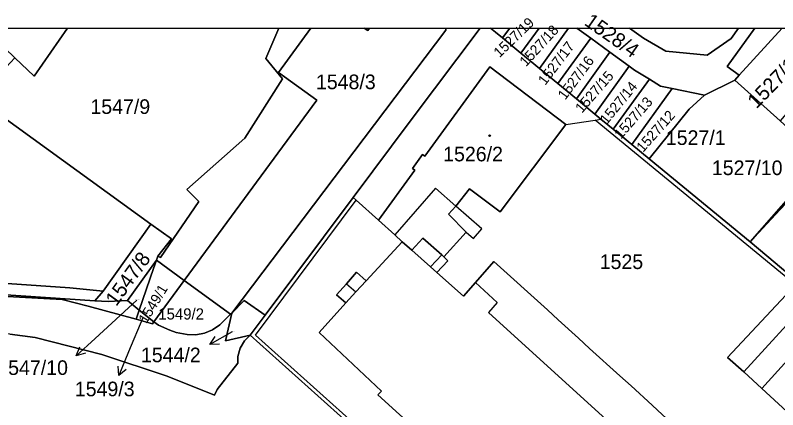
# Model space of a CAD drawing. Extents: x -598934 to -598196, y -1162208 to -1161502.
# Drawn here: x -598774.9 to -598686.2, y -1161549.6 to -1161503.7 of the extents above; entities that cross this region are included whole.
import ezdxf

# ---------------------------------------------------------------- set-up
doc = ezdxf.new("R2010")
doc.units = 0
for name, color, linetype in [('KN_CAR_KR', 7, 'Continuous'), ('KN_KULTURY', 7, 'Continuous'), ('KN_PARC_CIS_POM', 7, 'Continuous'), ('KN_PARC_CIS_POZ', 7, 'Continuous'), ('KN_PARC_CIS_STAV', 7, 'Continuous'), ('KN_PARC_PLOCHA', 7, 'Continuous'), ('PARC_C_SIPKA', 7, 'Continuous'), ('parcely_l', 7, 'Continuous')]:
    doc.layers.add(name, color=color, linetype=linetype)

msp = doc.modelspace()

# ---------------------------------------------------------------- linework, layer by layer
at = {"layer": 'KN_CAR_KR'}
for points in [[(-598710.83, -1161516.41), (-598707.43, -1161515.89)], [(-598707.43, -1161515.89), (-598706.75, -1161515.78)], [(-598684.14, -1161535.08), (-598707.43, -1161515.89)], [(-598726.01, -1161523.82), (-598730.74, -1161529.25)], [(-598723.64, -1161525.9), (-598726.01, -1161523.82)], [(-598746.92, -1161540.94), (-598735.22, -1161525.21)], [(-598735.56, -1161524.9), (-598735.22, -1161525.21)], [(-598735.22, -1161525.21), (-598732.63, -1161527.55)], [(-598720.59, -1161528.56), (-598723.64, -1161525.9)], [(-598722.41, -1161528.95), (-598721.57, -1161529.68)], [(-598721.57, -1161529.68), (-598720.59, -1161528.56)], [(-598728.73, -1161531.02), (-598726.58, -1161532.98)], [(-598726.58, -1161532.98), (-598725.27, -1161531.59)], [(-598726.58, -1161532.98), (-598725.82, -1161533.64)], [(-598736.36, -1161534.97), (-598735.27, -1161535.88)], [(-598735.27, -1161535.88), (-598734.05, -1161534.6)], [(-598721.34, -1161534.81), (-598718.81, -1161537.11)], [(-598736.43, -1161537.17), (-598735.27, -1161535.88)], [(-598690.13, -1161545.2), (-598682.28, -1161536.6)], [(-598718.81, -1161537.11), (-598719.81, -1161538.29)], [(-598719.81, -1161538.29), (-598700.16, -1161556.18)], [(-598688.04, -1161547.15), (-598679.81, -1161538.05)], [(-598713.19, -1161571.18), (-598746.92, -1161540.94)]]:
    msp.add_lwpolyline(points, dxfattribs=at)
at = {"layer": 'KN_KULTURY'}
for radius in [0.09, 0.0398]:
    msp.add_circle((-598719.7, -1161517.71), radius, dxfattribs=at)
at = {"layer": 'KN_PARC_PLOCHA'}
for points in [[(-598758.28, -1161531.72), (-598756.68, -1161529.73), (-598759.09, -1161528.02), (-598776.32, -1161515.51), (-598780.81, -1161514.88), (-598780.35, -1161514.34), (-598775.91, -1161509.73), (-598774.9, -1161508.67), (-598772.65, -1161510.8), (-598768.804, -1161505.182), (-598744.218, -1161505.182), (-598745.73, -1161508.71), (-598743.78, -1161511.08), (-598748.16, -1161518.02), (-598754.92, -1161523.98), (-598753.52, -1161525.38), (-598757.99, -1161531.9)], [(-598774.9, -1161508.67), (-598778.521, -1161505.182), (-598768.804, -1161505.182), (-598772.65, -1161510.8)], [(-598739.81, -1161513.56), (-598755.21, -1161534.56), (-598758.45, -1161532.21), (-598758.28, -1161531.72), (-598757.99, -1161531.9), (-598753.52, -1161525.38), (-598754.92, -1161523.98), (-598748.16, -1161518.02), (-598743.78, -1161511.08), (-598745.73, -1161508.71), (-598744.218, -1161505.182), (-598740.505, -1161505.182), (-598744.24, -1161510.34)], [(-598749.66, -1161538.35), (-598749.85, -1161538.48), (-598755.21, -1161534.56), (-598739.81, -1161513.56), (-598744.24, -1161510.34), (-598740.505, -1161505.182), (-598734.281, -1161505.182), (-598733.87, -1161505.48), (-598733.653, -1161505.182), (-598724.79, -1161505.182), (-598724.8, -1161505.44)], [(-598745.81, -1161538.62), (-598748.23, -1161536.88), (-598749.66, -1161538.35), (-598724.8, -1161505.44), (-598724.79, -1161505.182), (-598720.816, -1161505.182), (-598728.81, -1161515.85), (-598735.56, -1161524.9)], [(-598733.653, -1161505.182), (-598733.87, -1161505.48), (-598734.281, -1161505.182)], [(-598718.2, -1161506.34), (-598719.01, -1161505.67), (-598719.604, -1161505.182), (-598717.36, -1161505.182)], [(-598716.05, -1161508.11), (-598718.2, -1161506.34), (-598717.36, -1161505.182), (-598713.934, -1161505.182)], [(-598713.9, -1161509.88), (-598716.05, -1161508.11), (-598713.934, -1161505.182), (-598710.515, -1161505.182)], [(-598707.94, -1161506.37), (-598711.76, -1161511.65), (-598713.9, -1161509.88), (-598710.515, -1161505.182), (-598709.57, -1161505.182)], [(-598690.67, -1161510.67), (-598691.19, -1161511.24), (-598694.69, -1161513.01), (-598698.46, -1161512.22), (-598699.82, -1161511.93), (-598701.12, -1161511.13), (-598702.83, -1161510.09), (-598703.46, -1161509.63), (-598705.7, -1161508), (-598707.94, -1161506.37), (-598709.57, -1161505.182), (-598703.443, -1161505.182), (-598701.79, -1161506.37), (-598699.19, -1161507.89), (-598694.39, -1161508.34), (-598691.62, -1161506.42), (-598690.74, -1161505.182), (-598688.839, -1161505.182), (-598692.07, -1161509.66)], [(-598703.443, -1161505.182), (-598690.74, -1161505.182), (-598691.62, -1161506.42), (-598694.39, -1161508.34), (-598699.19, -1161507.89), (-598701.79, -1161506.37)], [(-598690.67, -1161510.67), (-598692.07, -1161509.66), (-598688.839, -1161505.182), (-598685.682, -1161505.182)], [(-598679.29, -1161508.89), (-598681.5, -1161511.01), (-598683.66, -1161513.34), (-598685.92, -1161515.99), (-598691.19, -1161511.24), (-598690.67, -1161510.67), (-598685.682, -1161505.182), (-598683.293, -1161505.182)], [(-598705.7, -1161508), (-598709.61, -1161513.42), (-598711.76, -1161511.65), (-598707.94, -1161506.37)], [(-598703.46, -1161509.63), (-598707.46, -1161515.19), (-598709.61, -1161513.42), (-598705.7, -1161508)], [(-598784.46, -1161519.18), (-598780.81, -1161514.88), (-598776.32, -1161515.51), (-598759.09, -1161528.02), (-598764.63, -1161535.79), (-598768.53, -1161535.41), (-598797.22, -1161533.44), (-598803.42, -1161532.39), (-598806.83, -1161531.59), (-598811.84, -1161530.11), (-598815.58, -1161528.74), (-598818.64, -1161527.27), (-598812.03, -1161518.31), (-598805.79, -1161510.18), (-598804.43, -1161511.1), (-598802.29, -1161510.38), (-598799.96, -1161510), (-598797.69, -1161510.09), (-598796.07, -1161510.41), (-598793.19, -1161511.82), (-598791.32, -1161513.23), (-598790.28, -1161514.28), (-598789.08, -1161516.12), (-598787.81, -1161519.11)], [(-598725.04, -1161531.81), (-598725.27, -1161531.59), (-598727.45, -1161529.65), (-598728.73, -1161531.02), (-598729.85, -1161530.05), (-598730.74, -1161529.25), (-598732.63, -1161527.55), (-598728.39, -1161521.72), (-598728.68, -1161521.52), (-598727.5, -1161519.9), (-598727.22, -1161520.1), (-598719.66, -1161509.71), (-598710.83, -1161516.41), (-598718.49, -1161526.57), (-598722.04, -1161523.9), (-598723.64, -1161525.9), (-598724.47, -1161526.85), (-598722.41, -1161528.95)], [(-598701.12, -1161511.13), (-598705.32, -1161516.95), (-598706.75, -1161515.78), (-598707.46, -1161515.19), (-598703.46, -1161509.63), (-598702.83, -1161510.09)], [(-598698.46, -1161512.22), (-598703.17, -1161518.72), (-598705.32, -1161516.95), (-598701.12, -1161511.13), (-598699.82, -1161511.93)], [(-598685.92, -1161515.99), (-598681, -1161520.47), (-598689.39, -1161530.06), (-598701.14, -1161520.39), (-598696.48, -1161514.62), (-598694.69, -1161513.01), (-598691.19, -1161511.24)], [(-598694.69, -1161513.01), (-598696.48, -1161514.62), (-598701.14, -1161520.39), (-598703.17, -1161518.72), (-598698.46, -1161512.22)], [(-598676.32, -1161516.24), (-598685.94, -1161526.36), (-598689.39, -1161530.06), (-598681, -1161520.47), (-598678.59, -1161517.73), (-598676.83, -1161515.79)], [(-598656.9, -1161534.24), (-598668.32, -1161547.09), (-598668.69, -1161546.9), (-598679.58, -1161538.19), (-598679.81, -1161538.05), (-598681.93, -1161536.28), (-598683.8, -1161534.76), (-598689.39, -1161530.06), (-598685.94, -1161526.36), (-598676.32, -1161516.24), (-598667.18, -1161524.65)], [(-598758.28, -1161531.72), (-598758.45, -1161532.21), (-598761.81, -1161536.9), (-598764.05, -1161537.02), (-598765.61, -1161536.92), (-598764.63, -1161535.79), (-598759.09, -1161528.02), (-598756.68, -1161529.73)], [(-598812.29, -1161531.38), (-598807.16, -1161532.91), (-598800.29, -1161534.3), (-598794.34, -1161535), (-598765.61, -1161536.92), (-598764.05, -1161537.02), (-598761.81, -1161536.9), (-598760.45, -1161538.01), (-598760.82, -1161539.08), (-598766.39, -1161537.57), (-598769.42, -1161536.76), (-598780.05, -1161536.18), (-598787.24, -1161536.14), (-598793.93, -1161535.43), (-598805.37, -1161534.38), (-598812.72, -1161531.83), (-598819.51, -1161528.42)], [(-598764.63, -1161535.79), (-598765.61, -1161536.92), (-598794.34, -1161535), (-598800.29, -1161534.3), (-598807.16, -1161532.91), (-598806.83, -1161531.59), (-598803.42, -1161532.39), (-598797.22, -1161533.44), (-598768.53, -1161535.41)], [(-598760.45, -1161538.01), (-598761.81, -1161536.9), (-598758.45, -1161532.21), (-598758.79, -1161533.17)], [(-598755.21, -1161534.56), (-598758.75, -1161539.39), (-598760.45, -1161538.01), (-598758.79, -1161533.17), (-598758.45, -1161532.21)], [(-598749.85, -1161538.48), (-598751.07, -1161539.71), (-598751.91, -1161540.31), (-598752.86, -1161540.7), (-598753.86, -1161540.88), (-598754.87, -1161540.85), (-598756.17, -1161540.61), (-598756.9, -1161540.34), (-598758.21, -1161539.76), (-598758.75, -1161539.39), (-598755.21, -1161534.56)], [(-598668.69, -1161546.9), (-598677.31, -1161556.9), (-598679.85, -1161554.66), (-598680.37, -1161555.18), (-598682.21, -1161553.52), (-598681.73, -1161552.97), (-598688.04, -1161547.15), (-598690.13, -1161545.2), (-598692.02, -1161543.52), (-598684.14, -1161535.08), (-598683.8, -1161534.76), (-598681.93, -1161536.28), (-598679.81, -1161538.05), (-598679.58, -1161538.19)], [(-598745.81, -1161538.62), (-598747.54, -1161540.94), (-598750.4, -1161541.58), (-598749.66, -1161538.35), (-598748.23, -1161536.88)], [(-598758.75, -1161539.39), (-598758.91, -1161539.61), (-598760.82, -1161539.08), (-598760.45, -1161538.01)]]:
    msp.add_lwpolyline(points, close=True, dxfattribs=at)
for points in [[(-598718.31, -1161567.16), (-598747.54, -1161540.94), (-598745.81, -1161538.62), (-598735.56, -1161524.9), (-598728.81, -1161515.85), (-598720.816, -1161505.182), (-598719.604, -1161505.182), (-598719.01, -1161505.67), (-598718.2, -1161506.34), (-598716.05, -1161508.11), (-598713.9, -1161509.88), (-598711.76, -1161511.65), (-598709.61, -1161513.42), (-598707.46, -1161515.19), (-598706.75, -1161515.78), (-598705.32, -1161516.95), (-598703.17, -1161518.72), (-598701.14, -1161520.39), (-598689.39, -1161530.06), (-598683.8, -1161534.76)], [(-598699.58, -1161550.19), (-598700.78, -1161549.06), (-598703.25, -1161546.81), (-598704.54, -1161545.68), (-598708.07, -1161542.47), (-598709.35, -1161541.28), (-598711.73, -1161539.15), (-598712.96, -1161537.99), (-598719.21, -1161532.36), (-598721.34, -1161534.81), (-598722.74, -1161536.38), (-598725.82, -1161533.64), (-598724.54, -1161532.27), (-598725.04, -1161531.81), (-598722.41, -1161528.95), (-598724.47, -1161526.85), (-598723.64, -1161525.9), (-598722.04, -1161523.9), (-598718.49, -1161526.57), (-598710.83, -1161516.41), (-598719.66, -1161509.71), (-598727.22, -1161520.1), (-598727.5, -1161519.9), (-598728.68, -1161521.52), (-598728.39, -1161521.72), (-598732.63, -1161527.55), (-598730.74, -1161529.25), (-598729.85, -1161530.05), (-598734.05, -1161534.6), (-598735.16, -1161533.58), (-598736.36, -1161534.97), (-598737.49, -1161536.23), (-598736.43, -1161537.17), (-598739.51, -1161540.6), (-598732.26, -1161547.43), (-598732.68, -1161547.89), (-598710.43, -1161568.09)], [(-598710.43, -1161568.09), (-598732.68, -1161547.89), (-598732.26, -1161547.43), (-598739.51, -1161540.6), (-598736.43, -1161537.17), (-598737.49, -1161536.23), (-598736.36, -1161534.97), (-598735.16, -1161533.58), (-598734.05, -1161534.6), (-598729.85, -1161530.05), (-598728.73, -1161531.02), (-598727.45, -1161529.65), (-598725.27, -1161531.59), (-598725.04, -1161531.81), (-598724.54, -1161532.27), (-598725.82, -1161533.64), (-598722.74, -1161536.38), (-598721.34, -1161534.81), (-598719.21, -1161532.36), (-598712.96, -1161537.99), (-598711.73, -1161539.15), (-598709.35, -1161541.28), (-598708.07, -1161542.47), (-598704.54, -1161545.68), (-598703.25, -1161546.81), (-598700.78, -1161549.06), (-598699.58, -1161550.19)], [(-598684.14, -1161535.08), (-598692.02, -1161543.52), (-598690.13, -1161545.2), (-598688.04, -1161547.15), (-598681.73, -1161552.97)], [(-598780.05, -1161536.18), (-598769.42, -1161536.76), (-598766.39, -1161537.57), (-598760.82, -1161539.08), (-598758.91, -1161539.61), (-598758.75, -1161539.39), (-598758.21, -1161539.76), (-598756.9, -1161540.34), (-598756.17, -1161540.61), (-598754.87, -1161540.85), (-598753.86, -1161540.88), (-598752.86, -1161540.7), (-598751.91, -1161540.31), (-598751.07, -1161539.71), (-598749.85, -1161538.48), (-598749.66, -1161538.35), (-598750.4, -1161541.58), (-598747.54, -1161540.94), (-598748.19, -1161541.59), (-598748.71, -1161542.44), (-598748.97, -1161543.41), (-598748.98, -1161544.17), (-598751.4, -1161547.24), (-598751.7, -1161547.91), (-598757.19, -1161545.72), (-598764.79, -1161543.19), (-598772.55, -1161541.22), (-598775.51, -1161540.82)], [(-598775.51, -1161540.82), (-598772.55, -1161541.22), (-598764.79, -1161543.19), (-598757.19, -1161545.72), (-598751.7, -1161547.91), (-598751.4, -1161547.24), (-598748.98, -1161544.17), (-598748.97, -1161543.41), (-598748.71, -1161542.44), (-598748.19, -1161541.59), (-598747.54, -1161540.94), (-598718.31, -1161567.16), (-598713.5, -1161571.51), (-598705.75, -1161578.52), (-598701.74, -1161583.54), (-598699.41, -1161586.46), (-598694.17, -1161593.02), (-598696.41, -1161595.1), (-598697.8, -1161597.55), (-598697.38, -1161599.8), (-598691.61, -1161616.39), (-598686.46, -1161632.58), (-598684.05, -1161640.04)]]:
    msp.add_lwpolyline(points, dxfattribs=at)
at = {"layer": 'PARC_C_SIPKA'}
for points in [[(-598760.72, -1161536.84), (-598765.56, -1161541.31), (-598767.764, -1161543.345)], [(-598760.04, -1161538.91), (-598761.68, -1161542.87), (-598762.829, -1161545.641)], [(-598749.62, -1161540.54), (-598752.231, -1161542.018)], [(-598751.114, -1161541.96), (-598752.231, -1161542.018), (-598751.607, -1161541.09)], [(-598766.69, -1161543.034), (-598767.764, -1161543.345), (-598767.369, -1161542.299)], [(-598761.984, -1161544.909), (-598762.829, -1161545.641), (-598762.908, -1161544.526)]]:
    msp.add_lwpolyline(points, dxfattribs=at)
at = {"layer": 'parcely_l'}
for points in [[(-598778.521, -1161505.182), (-598768.804, -1161505.182)], [(-598774.9, -1161508.67), (-598772.65, -1161510.8), (-598768.804, -1161505.182)], [(-598768.804, -1161505.182), (-598744.218, -1161505.182)], [(-598744.218, -1161505.182), (-598745.73, -1161508.71), (-598743.78, -1161511.08), (-598748.16, -1161518.02), (-598754.92, -1161523.98), (-598753.52, -1161525.38), (-598757.99, -1161531.9), (-598758.28, -1161531.72)], [(-598749.66, -1161538.35), (-598724.8, -1161505.44), (-598724.79, -1161505.182)], [(-598720.816, -1161505.182), (-598728.81, -1161515.85), (-598735.56, -1161524.9), (-598745.81, -1161538.62)], [(-598740.505, -1161505.182), (-598744.24, -1161510.34), (-598739.81, -1161513.56)], [(-598744.218, -1161505.182), (-598740.505, -1161505.182)], [(-598740.505, -1161505.182), (-598734.281, -1161505.182)], [(-598733.653, -1161505.182), (-598733.87, -1161505.48), (-598734.281, -1161505.182)], [(-598734.281, -1161505.182), (-598733.653, -1161505.182)], [(-598733.653, -1161505.182), (-598724.79, -1161505.182)], [(-598724.79, -1161505.182), (-598720.816, -1161505.182)], [(-598720.816, -1161505.182), (-598719.604, -1161505.182)], [(-598719.604, -1161505.182), (-598719.01, -1161505.67), (-598718.2, -1161506.34)], [(-598719.604, -1161505.182), (-598717.36, -1161505.182)], [(-598718.2, -1161506.34), (-598717.36, -1161505.182)], [(-598717.36, -1161505.182), (-598713.934, -1161505.182)], [(-598713.934, -1161505.182), (-598716.05, -1161508.11)], [(-598713.934, -1161505.182), (-598710.515, -1161505.182)], [(-598710.515, -1161505.182), (-598713.9, -1161509.88)], [(-598710.515, -1161505.182), (-598709.57, -1161505.182)], [(-598707.94, -1161506.37), (-598709.57, -1161505.182)], [(-598709.57, -1161505.182), (-598703.443, -1161505.182)], [(-598703.443, -1161505.182), (-598701.79, -1161506.37), (-598699.19, -1161507.89), (-598694.39, -1161508.34), (-598691.62, -1161506.42), (-598690.74, -1161505.182)], [(-598703.443, -1161505.182), (-598690.74, -1161505.182)], [(-598688.839, -1161505.182), (-598692.07, -1161509.66), (-598690.67, -1161510.67)], [(-598690.74, -1161505.182), (-598688.839, -1161505.182)], [(-598685.682, -1161505.182), (-598690.67, -1161510.67)], [(-598688.839, -1161505.182), (-598685.682, -1161505.182)], [(-598716.05, -1161508.11), (-598718.2, -1161506.34)], [(-598707.94, -1161506.37), (-598711.76, -1161511.65)], [(-598705.7, -1161508), (-598707.94, -1161506.37)], [(-598713.9, -1161509.88), (-598716.05, -1161508.11)], [(-598709.61, -1161513.42), (-598705.7, -1161508)], [(-598703.46, -1161509.63), (-598705.7, -1161508)], [(-598729.85, -1161530.05), (-598730.74, -1161529.25), (-598732.63, -1161527.55), (-598728.39, -1161521.72), (-598728.68, -1161521.52), (-598727.5, -1161519.9), (-598727.22, -1161520.1), (-598719.66, -1161509.71), (-598710.83, -1161516.41), (-598718.49, -1161526.57), (-598722.04, -1161523.9), (-598723.64, -1161525.9), (-598724.47, -1161526.85), (-598722.41, -1161528.95), (-598725.04, -1161531.81)], [(-598711.76, -1161511.65), (-598713.9, -1161509.88)], [(-598703.46, -1161509.63), (-598707.46, -1161515.19)], [(-598701.12, -1161511.13), (-598702.83, -1161510.09), (-598703.46, -1161509.63)], [(-598701.12, -1161511.13), (-598705.32, -1161516.95)], [(-598698.46, -1161512.22), (-598699.82, -1161511.93), (-598701.12, -1161511.13)], [(-598691.19, -1161511.24), (-598694.69, -1161513.01)], [(-598690.67, -1161510.67), (-598691.19, -1161511.24)], [(-598691.19, -1161511.24), (-598685.92, -1161515.99)], [(-598709.61, -1161513.42), (-598711.76, -1161511.65)], [(-598703.17, -1161518.72), (-598698.46, -1161512.22)], [(-598694.69, -1161513.01), (-598696.48, -1161514.62), (-598701.14, -1161520.39)], [(-598694.69, -1161513.01), (-598698.46, -1161512.22)], [(-598739.81, -1161513.56), (-598755.21, -1161534.56)], [(-598707.46, -1161515.19), (-598709.61, -1161513.42)], [(-598759.09, -1161528.02), (-598776.32, -1161515.51), (-598780.81, -1161514.88)], [(-598705.32, -1161516.95), (-598706.75, -1161515.78), (-598707.46, -1161515.19)], [(-598676.32, -1161516.24), (-598685.94, -1161526.36), (-598689.39, -1161530.06)], [(-598703.17, -1161518.72), (-598705.32, -1161516.95)], [(-598701.14, -1161520.39), (-598703.17, -1161518.72)], [(-598701.14, -1161520.39), (-598689.39, -1161530.06)], [(-598689.39, -1161530.06), (-598681, -1161520.47)], [(-598764.63, -1161535.79), (-598759.09, -1161528.02)], [(-598758.28, -1161531.72), (-598756.68, -1161529.73), (-598759.09, -1161528.02)], [(-598819.51, -1161528.42), (-598812.72, -1161531.83), (-598805.37, -1161534.38), (-598793.93, -1161535.43), (-598787.24, -1161536.14), (-598780.05, -1161536.18), (-598769.42, -1161536.76), (-598766.39, -1161537.57), (-598760.82, -1161539.08)], [(-598725.04, -1161531.81), (-598725.27, -1161531.59), (-598727.45, -1161529.65), (-598728.73, -1161531.02), (-598729.85, -1161530.05)], [(-598729.85, -1161530.05), (-598734.05, -1161534.6), (-598735.16, -1161533.58), (-598736.36, -1161534.97), (-598737.49, -1161536.23), (-598736.43, -1161537.17), (-598739.51, -1161540.6), (-598732.26, -1161547.43), (-598732.68, -1161547.89), (-598710.43, -1161568.09), (-598713.19, -1161571.18), (-598713.5, -1161571.51)], [(-598683.8, -1161534.76), (-598689.39, -1161530.06)], [(-598806.83, -1161531.59), (-598803.42, -1161532.39), (-598797.22, -1161533.44), (-598768.53, -1161535.41), (-598764.63, -1161535.79)], [(-598758.45, -1161532.21), (-598761.81, -1161536.9)], [(-598760.45, -1161538.01), (-598758.79, -1161533.17), (-598758.45, -1161532.21)], [(-598758.45, -1161532.21), (-598758.28, -1161531.72)], [(-598755.21, -1161534.56), (-598758.45, -1161532.21)], [(-598683.96, -1161564.33), (-598696.84, -1161552.69), (-598699.58, -1161550.19), (-598700.78, -1161549.06), (-598703.25, -1161546.81), (-598704.54, -1161545.68), (-598708.07, -1161542.47), (-598709.35, -1161541.28), (-598711.73, -1161539.15), (-598712.96, -1161537.99), (-598719.21, -1161532.36), (-598721.34, -1161534.81), (-598722.74, -1161536.38), (-598725.82, -1161533.64), (-598724.54, -1161532.27), (-598725.04, -1161531.81)], [(-598765.61, -1161536.92), (-598794.34, -1161535), (-598800.29, -1161534.3), (-598807.16, -1161532.91)], [(-598758.75, -1161539.39), (-598755.21, -1161534.56)], [(-598755.21, -1161534.56), (-598749.85, -1161538.48)], [(-598677.31, -1161556.9), (-598679.85, -1161554.66), (-598680.37, -1161555.18), (-598682.21, -1161553.52), (-598681.73, -1161552.97), (-598688.04, -1161547.15), (-598690.13, -1161545.2), (-598692.02, -1161543.52), (-598684.14, -1161535.08), (-598683.8, -1161534.76)], [(-598764.63, -1161535.79), (-598765.61, -1161536.92)], [(-598761.81, -1161536.9), (-598764.05, -1161537.02), (-598765.61, -1161536.92)], [(-598761.81, -1161536.9), (-598760.45, -1161538.01)], [(-598745.81, -1161538.62), (-598748.23, -1161536.88), (-598749.66, -1161538.35)], [(-598760.82, -1161539.08), (-598760.45, -1161538.01)], [(-598760.45, -1161538.01), (-598758.75, -1161539.39)], [(-598749.85, -1161538.48), (-598751.07, -1161539.71), (-598751.91, -1161540.31), (-598752.86, -1161540.7), (-598753.86, -1161540.88), (-598754.87, -1161540.85), (-598756.17, -1161540.61), (-598756.9, -1161540.34), (-598758.21, -1161539.76), (-598758.75, -1161539.39)], [(-598749.66, -1161538.35), (-598750.4, -1161541.58), (-598747.54, -1161540.94)], [(-598749.66, -1161538.35), (-598749.85, -1161538.48)], [(-598745.81, -1161538.62), (-598747.54, -1161540.94)], [(-598758.75, -1161539.39), (-598758.91, -1161539.61), (-598760.82, -1161539.08)], [(-598747.54, -1161540.94), (-598748.19, -1161541.59), (-598748.71, -1161542.44), (-598748.97, -1161543.41), (-598748.98, -1161544.17), (-598751.4, -1161547.24), (-598751.7, -1161547.91), (-598757.19, -1161545.72), (-598764.79, -1161543.19), (-598772.55, -1161541.22), (-598775.51, -1161540.82), (-598785.79, -1161540.44)], [(-598747.54, -1161540.94), (-598718.31, -1161567.16), (-598713.5, -1161571.51)]]:
    msp.add_lwpolyline(points, dxfattribs=at)

# ---------------------------------------------------------------- texts
at = {"layer": 'KN_PARC_CIS_POM'}
for s, p in [('1547/10', (-598760.878, -1161536.84)), ('1549/3', (-598760.173, -1161538.91)), ('1544/2', (-598749.753, -1161540.54))]:
    msp.add_text(s, height=0.1, dxfattribs=at).set_placement(p)
at = {"layer": 'KN_PARC_CIS_POZ'}
for s, height, rotation, p in [('1527/19', 1.19, 44.09944, (-598718.546, -1161508.698)), ('1528/4', 1.7, 324.90048, (-598708.794, -1161504.747)), ('1527/18', 1.19, 47.49876, (-598715.463, -1161509.748)), ('1527/17', 1.19, 52.80021, (-598713.23, -1161511.919)), ('1527/16', 1.19, 53.5007, (-598710.903, -1161513.626)), ('1527/11', 1.7, 45.69999, (-598688.671, -1161514.663)), ('1527/15', 1.19, 48.90078, (-598708.961, -1161515.161)), ('1527/14', 1.19, 50.79964, (-598706.065, -1161516.486)), ('1527/13', 1.19, 49.0012, (-598704.424, -1161518.184)), ('1527/12', 1.19, 48.50012, (-598701.857, -1161519.729)), ('1547/8', 1.7, 53.99922, (-598763.121, -1161537.667)), ('1549/1', 1.19, 58.67071, (-598759.603, -1161539.66))]:
    msp.add_text(s, height=height, rotation=rotation, dxfattribs=at).set_placement(p)
for s, height, p in [('1547/9', 1.7, (-598766.127, -1161515.18)), ('1527/1', 1.7, (-598699.207, -1161518.79)), ('1527/10', 1.7, (-598693.852, -1161522.3)), ('1525', 1.7, (-598706.897, -1161533.23)), ('1549/2', 1.3, (-598758.233, -1161539.11)), ('1544/2', 1.7, (-598760.247, -1161544.08)), ('1547/10', 1.7, (-598776.952, -1161545.56)), ('1549/3', 1.7, (-598767.937, -1161548.04))]:
    msp.add_text(s, height=height, dxfattribs=at).set_placement(p)
at = {"layer": 'KN_PARC_CIS_STAV'}
for s, p in [('1548/3', (-598739.897, -1161512.3)), ('1526/2', (-598725.102, -1161520.7))]:
    msp.add_text(s, height=1.7, dxfattribs=at).set_placement(p)

doc.saveas('drawing.dxf')
